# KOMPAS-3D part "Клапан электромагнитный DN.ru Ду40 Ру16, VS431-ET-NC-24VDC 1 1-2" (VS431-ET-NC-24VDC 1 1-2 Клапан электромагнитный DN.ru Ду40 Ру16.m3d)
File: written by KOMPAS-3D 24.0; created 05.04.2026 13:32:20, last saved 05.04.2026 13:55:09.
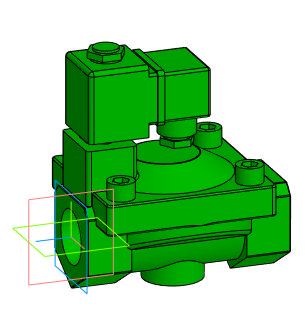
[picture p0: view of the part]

Document properties: Автор: artio; Полное имя файла: C:\Users\artio\OneDrive\Рабочий стол\Клапан электромагнитный DN.ru\VS431\VS431-ET-NC\VS431-ET-NC-24VDC\Ду40\VS431-ET-NC-24VDC 1 1-2 Клапан электромагнитный DN.ru Ду40 Ру16.m3d

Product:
- Body: Тело 1  | qty 1
    Масса: 3.859459
- Part/product: Клапан электромагнитный DN.ru Ду40 Ру16  | designation VS431-ET-NC-24VDC 1 1-2
    Масса: 2.285
    Раздел спецификации: Прочие изделия
    Примечание: D130-04744
    additional columns: ef56311e-7521-43dc-8291-0e6108b3d81d; artio; c; Шероховатость не задана; Да

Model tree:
1. Операция без истории:1

Expressions: VS431-ET-NC-24VDC 1 1-2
